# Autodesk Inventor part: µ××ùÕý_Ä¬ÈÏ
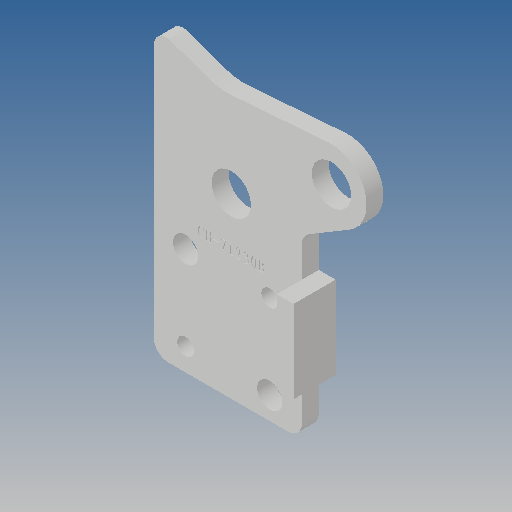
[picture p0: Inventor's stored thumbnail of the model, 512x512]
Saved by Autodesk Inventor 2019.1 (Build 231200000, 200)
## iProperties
Created: 2012-10
Part Number: µ××ùÕý_Ä¬ÈÏ
Material: Ogólny
Document SubType Name: Modeling
Designer: CADENGINEERING4
Density: 1 g/cm^3
Appearance: Domyślna
Author: CADENGINEERING4
Revision Number: ÈÎºÎ
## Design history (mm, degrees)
feature "NONE"
node "Bryła1"
